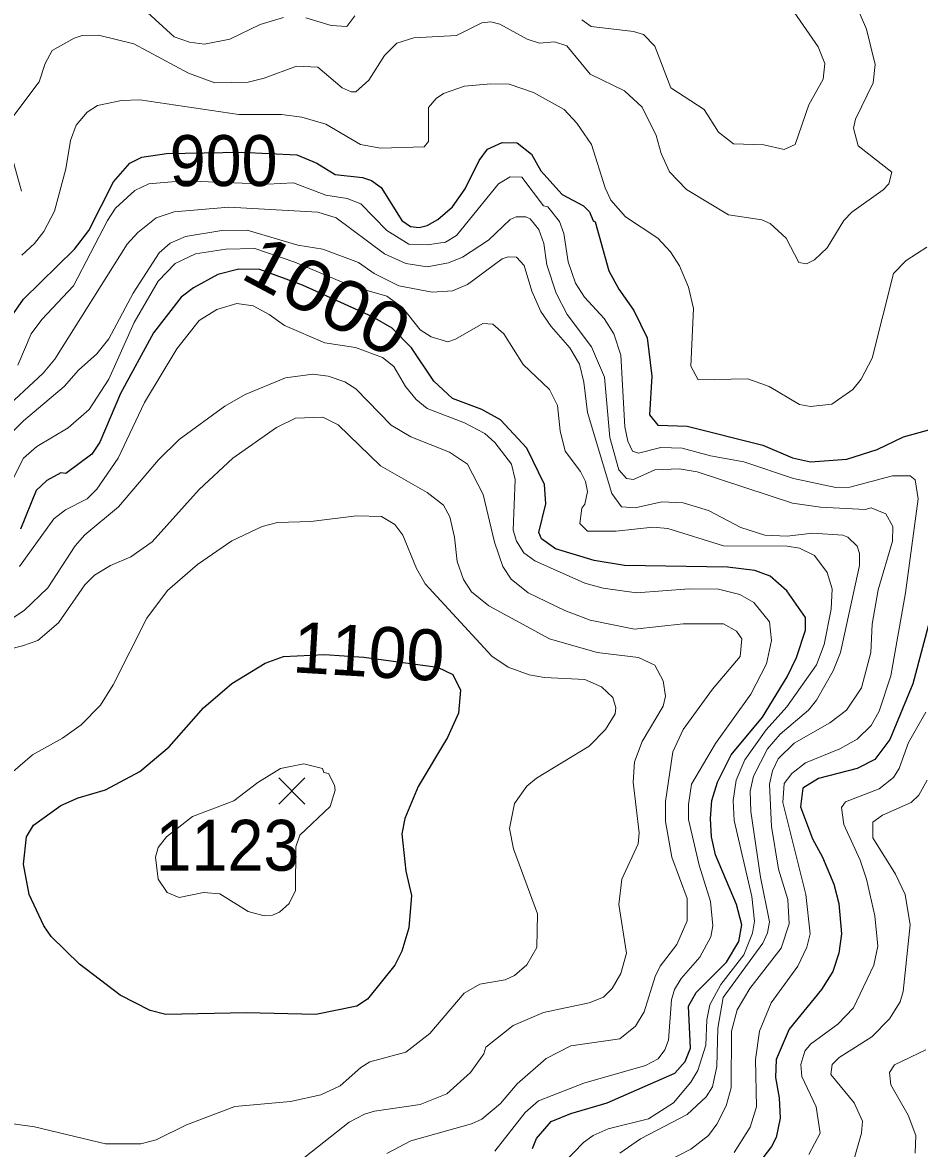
# Model space of a CAD drawing. Extents: x 265 to 291.4, y 7731.5 to 7759.6.
# Drawn here: x 282.452 to 283.863, y 7748.958 to 7750.728 of the extents above; entities that cross this region are included whole.
import ezdxf
from ezdxf.enums import TextEntityAlignment as Align

# ---------------------------------------------------------------- set-up
doc = ezdxf.new("R2010")
doc.units = 0
doc.header["$LTSCALE"] = 0.032
for name, color, linetype, lineweight in [('1', 7, 'Continuous', 25), ('2', 7, 'Continuous', 13), ('21', 7, 'Continuous', 25), ('61', 7, 'Continuous', 13)]:
    doc.layers.add(name, color=color, linetype=linetype, lineweight=lineweight)

msp = doc.modelspace()

# ---------------------------------------------------------------- linework, layer by layer
at = {"layer": '1'}
for points in [[(282.3987, 7750.2149), (282.4536, 7750.2929), (282.534, 7750.3716), (282.5562, 7750.401), (282.5952, 7750.4774), (282.6207, 7750.5068), (282.6398, 7750.5164), (282.6787, 7750.522), (282.7963, 7750.524), (282.8837, 7750.5201), (282.915, 7750.5068), (282.9436, 7750.4893), (282.9866, 7750.4845), (283.0009, 7750.4798), (283.016, 7750.4686), (283.0486, 7750.4169), (283.0622, 7750.4074), (283.0757, 7750.4058), (283.0884, 7750.409), (283.1051, 7750.4185), (283.1282, 7750.4384), (283.1481, 7750.4663), (283.1703, 7750.5108), (283.1831, 7750.5291), (283.2062, 7750.5394), (283.23, 7750.5386), (283.2523, 7750.5211), (283.2674, 7750.4949), (283.3008, 7750.4575), (283.3342, 7750.44), (283.3438, 7750.4304), (283.3493, 7750.4161), (283.3525, 7750.4146), (283.374, 7750.3374), (283.3899, 7750.3088), (283.4137, 7750.2754), (283.4344, 7750.2324), (283.4416, 7750.1719), (283.4384, 7750.1115), (283.4511, 7750.0948), (283.4973, 7750.0932), (283.6166, 7750.0637), (283.6628, 7750.0438), (283.6914, 7750.0375), (283.7487, 7750.0415), (283.7964, 7750.0566), (283.8377, 7750.0765), (283.8775, 7750.0876)], [(283.2539, 7748.958), (283.2602, 7748.9739), (283.2833, 7749.0002), (283.3143, 7749.0129), (283.3716, 7749.0296), (283.4782, 7749.0765), (283.4941, 7749.0949), (283.5028, 7749.1155), (283.4997, 7749.1815), (283.5116, 7749.203), (283.5593, 7749.2507), (283.5784, 7749.2834), (283.5832, 7749.3096), (283.5752, 7749.3415), (283.5418, 7749.4194), (283.5355, 7749.448), (283.5339, 7749.4767), (283.5363, 7749.5053), (283.545, 7749.534), (283.5665, 7749.5769), (283.6158, 7749.6358), (283.6548, 7749.6994), (283.6691, 7749.7296), (283.6834, 7749.7726), (283.6834, 7749.7925), (283.654, 7749.8347), (283.6277, 7749.8577), (283.6039, 7749.8664), (283.5609, 7749.872), (283.3987, 7749.8744), (283.3509, 7749.8824), (283.2905, 7749.9006), (283.2682, 7749.9166), (283.2642, 7749.9261), (283.2753, 7749.9715), (283.2729, 7750.0017), (283.2451, 7750.059), (283.2037, 7750.1035), (283.1743, 7750.1194), (283.1282, 7750.1369), (283.0987, 7750.164), (283.0637, 7750.2165), (283.0335, 7750.2475), (283.0027, 7750.2654), (282.8924, 7750.3153), (282.8254, 7750.3398), (282.7925, 7750.3405), (282.7591, 7750.3318), (282.7209, 7750.3111), (282.7018, 7750.296), (282.658, 7750.2404), (282.6063, 7750.1449), (282.5737, 7750.0685), (282.561, 7750.0494), (282.5204, 7750.0192), (282.5125, 7750.02), (282.4902, 7750.008), (282.4735, 7749.9921), (282.4488, 7749.9317)], [(283.8807, 7749.7949), (283.8521, 7749.6883), (283.8163, 7749.6008), (283.7924, 7749.5697), (283.7646, 7749.5554), (283.7041, 7749.5395), (283.6794, 7749.5244), (283.6755, 7749.495), (283.6946, 7749.4449), (283.7105, 7749.4162), (283.728, 7749.3733), (283.7359, 7749.343), (283.7399, 7749.2953), (283.7359, 7749.2651), (283.7264, 7749.2364), (283.7089, 7749.2078), (283.658, 7749.1458), (283.6373, 7749.098), (283.6365, 7749.0694), (283.6421, 7749.0376), (283.6436, 7749.0058), (283.6373, 7748.9755), (283.6301, 7748.9612), (283.5959, 7748.9166)]]:
    msp.add_lwpolyline(points, dxfattribs=at)
msp.add_lwpolyline([(282.6774, 7749.1687), (282.6526, 7749.1749), (282.6055, 7749.199), (282.5419, 7749.2476), (282.4973, 7749.2913), (282.4854, 7749.308), (282.4624, 7749.3574), (282.4536, 7749.4051), (282.4584, 7749.448), (282.4695, 7749.4663), (282.5125, 7749.4973), (282.5395, 7749.5093), (282.5825, 7749.522), (282.6366, 7749.5506), (282.6827, 7749.5896), (282.7368, 7749.6509), (282.7814, 7749.689), (282.8339, 7749.7209), (282.8625, 7749.7312), (282.9269, 7749.7344), (282.9887, 7749.7304), (283.1049, 7749.7145), (283.1288, 7749.7032), (283.1409, 7749.6787), (283.1377, 7749.6421), (283.1202, 7749.604), (283.0741, 7749.5268), (283.0534, 7749.4767), (283.0486, 7749.4528), (283.055, 7749.394), (283.0637, 7749.3558), (283.0598, 7749.3049), (283.0486, 7749.2683), (283.0375, 7749.246), (282.9945, 7749.1927), (282.9778, 7749.1815), (282.9134, 7749.1688), (282.8036, 7749.1712)], close=True, dxfattribs=at)
at = {"layer": '2'}
for points in [[(282.4989, 7750.6842), (282.5332, 7750.7033), (282.5459, 7750.7073), (282.5714, 7750.7081), (282.627, 7750.6946), (282.713, 7750.6484), (282.7543, 7750.6333), (282.8068, 7750.6341), (282.8323, 7750.6405), (282.8832, 7750.6596), (282.9166, 7750.658), (282.9548, 7750.6253), (282.9691, 7750.619), (282.9762, 7750.619), (282.9969, 7750.6373), (283.0216, 7750.6763), (283.0407, 7750.6953), (283.0677, 7750.7041), (283.1346, 7750.7073), (283.1743, 7750.7272), (283.1887, 7750.7288), (283.203, 7750.7256), (283.2459, 7750.7017), (283.265, 7750.6953), (283.2889, 7750.6977), (283.308, 7750.6914), (283.3446, 7750.6468), (283.3987, 7750.6206), (283.4265, 7750.5951), (283.4488, 7750.5506), (283.4567, 7750.522), (283.4694, 7750.4933), (283.4965, 7750.4655), (283.5625, 7750.4257), (283.615, 7750.4177), (283.6278, 7750.4122), (283.6532, 7750.3891), (283.6731, 7750.3509), (283.685, 7750.3485), (283.6978, 7750.3549), (283.7176, 7750.374), (283.7439, 7750.4169), (283.7566, 7750.4297), (283.8059, 7750.4647), (283.8147, 7750.4742), (283.8195, 7750.4925), (283.7662, 7750.5339), (283.759, 7750.5617), (283.7622, 7750.576), (283.79, 7750.6333), (283.7932, 7750.662), (283.7797, 7750.7176), (283.7574, 7750.7686)], [(283.6516, 7750.7654), (283.7033, 7750.6898), (283.7137, 7750.6635), (283.7113, 7750.6389), (283.689, 7750.5983), (283.6675, 7750.5363), (283.65, 7750.5283), (283.6182, 7750.5355), (283.5705, 7750.5371), (283.5466, 7750.5554), (283.5243, 7750.5912), (283.4718, 7750.6254), (283.4464, 7750.6906), (283.4289, 7750.7089), (283.413, 7750.7137), (283.3462, 7750.7216), (283.3318, 7750.732)], [(282.8625, 7750.7359), (282.8259, 7750.7248), (282.7782, 7750.7017), (282.7384, 7750.6938), (282.7145, 7750.6969), (282.6907, 7750.7057), (282.631, 7750.7598)], [(282.9747, 7750.7383), (282.9619, 7750.7216), (282.9373, 7750.7232), (282.8975, 7750.7351)], [(282.4504, 7750.4631), (282.4305, 7750.5347), (282.429, 7750.549), (282.4353, 7750.5776), (282.4783, 7750.6349), (282.4878, 7750.6635), (282.4989, 7750.6842)], [(283.8744, 7750.3748), (283.8417, 7750.3541), (283.8219, 7750.3334), (283.7884, 7750.2006), (283.7709, 7750.1672), (283.7582, 7750.1512), (283.7248, 7750.1282), (283.6914, 7750.1242), (283.6739, 7750.1274), (283.6262, 7750.156), (283.5928, 7750.1679), (283.5148, 7750.1664), (283.5029, 7750.1878), (283.5076, 7750.2785), (283.4997, 7750.3119), (283.4854, 7750.3454), (283.471, 7750.3676), (283.4511, 7750.3891), (283.4003, 7750.4225), (283.3772, 7750.4488), (283.3684, 7750.4679), (283.3469, 7750.5363), (283.3239, 7750.5697), (283.304, 7750.5912), (283.2555, 7750.6182), (283.2173, 7750.6309), (283.1887, 7750.6317), (283.1473, 7750.6277), (283.1139, 7750.6166), (283.1027, 7750.6086), (283.0908, 7750.5943), (283.0908, 7750.541), (283.0836, 7750.5323), (283.0152, 7750.5307), (282.9834, 7750.5363), (282.9293, 7750.5681), (282.8911, 7750.5792), (282.8593, 7750.5832), (282.7925, 7750.5832), (282.6366, 7750.6063), (282.6079, 7750.6055), (282.5697, 7750.5975), (282.5539, 7750.5872), (282.5363, 7750.5665), (282.5276, 7750.5426), (282.5204, 7750.4981), (282.5021, 7750.4313), (282.4854, 7750.3994), (282.4711, 7750.3804), (282.4512, 7750.3621)], [(282.4449, 7750.1894), (282.4655, 7750.2388), (282.4822, 7750.261), (282.5324, 7750.3143), (282.5857, 7750.4169), (282.5984, 7750.436), (282.6286, 7750.4639), (282.6509, 7750.4742), (282.7046, 7750.4793), (282.8371, 7750.474), (282.8784, 7750.4758), (282.9293, 7750.4567), (282.9627, 7750.4511), (282.9842, 7750.4432), (283.0248, 7750.401), (283.0598, 7750.3795), (283.0884, 7750.3787), (283.1171, 7750.3827), (283.1346, 7750.3931), (283.2006, 7750.4742), (283.2189, 7750.4853), (283.2372, 7750.4846), (283.2714, 7750.44), (283.2785, 7750.4384), (283.2968, 7750.4154), (283.3032, 7750.3963), (283.3103, 7750.3517), (283.3215, 7750.3183), (283.3358, 7750.296), (283.3668, 7750.2626), (283.3819, 7750.2388), (283.3931, 7750.2053), (283.3994, 7750.0924), (283.4042, 7750.0701), (283.4114, 7750.0542), (283.4209, 7750.051), (283.4559, 7750.0598), (283.4893, 7750.059), (283.5339, 7750.047), (283.5864, 7750.0375), (283.6644, 7750.0112), (283.7312, 7749.9969), (283.7534, 7749.9977), (283.8203, 7750.0152), (283.8481, 7750.0152), (283.8561, 7750.0089), (283.8608, 7749.9794), (283.8409, 7749.8315), (283.8179, 7749.701), (283.7996, 7749.6453), (283.7868, 7749.6231), (283.7646, 7749.6016), (283.7375, 7749.5864), (283.6834, 7749.5642), (283.662, 7749.5475), (283.65, 7749.5316), (283.6476, 7749.5021), (283.6842, 7749.3574), (283.6906, 7749.2953), (283.6858, 7749.2746), (283.6715, 7749.2444), (283.6293, 7749.1871), (283.611, 7749.1426), (283.6047, 7749.098), (283.6063, 7749.0233), (283.5967, 7748.9914), (283.5713, 7748.9517)], [(283.5585, 7749.0249), (283.5665, 7749.0535), (283.5673, 7749.1426), (283.576, 7749.176), (283.5959, 7749.2094), (283.6452, 7749.273), (283.658, 7749.3112), (283.6556, 7749.3494), (283.6413, 7749.3971), (283.6301, 7749.464), (283.627, 7749.5308), (283.6317, 7749.5515), (283.6405, 7749.5706), (283.6659, 7749.5952), (283.7216, 7749.627), (283.7479, 7749.6469), (283.7717, 7749.6819), (283.7861, 7749.7376), (283.7884, 7749.7822), (283.798, 7749.8362), (283.8203, 7749.9126), (283.821, 7749.9357), (283.8099, 7749.9556), (283.7869, 7749.9651), (283.7773, 7749.9627), (283.7073, 7749.9659), (283.6628, 7749.9723), (283.5132, 7750.0216), (283.4846, 7750.0264), (283.4464, 7750.0248), (283.413, 7750.0096), (283.4018, 7750.0112), (283.3899, 7750.0248), (283.3756, 7750.0757), (283.3676, 7750.1703), (283.3469, 7750.2181), (283.3088, 7750.269), (283.2913, 7750.3024), (283.2769, 7750.3469), (283.2722, 7750.3804), (283.2642, 7750.4026), (283.2507, 7750.4193), (283.2435, 7750.4225), (283.2284, 7750.4225), (283.2189, 7750.4185), (283.1847, 7750.3859), (283.1441, 7750.3589), (283.1218, 7750.3501), (283.0884, 7750.3437), (283.055, 7750.3493), (283.0216, 7750.3644), (282.9452, 7750.4209), (282.9166, 7750.4297), (282.7766, 7750.4376), (282.6907, 7750.4305), (282.662, 7750.4209), (282.6334, 7750.3978), (282.6167, 7750.3795), (282.5029, 7750.199), (282.4846, 7750.1767), (282.417, 7750.1139)], [(282.378, 7750.0272), (282.4536, 7750.1019), (282.5173, 7750.156), (282.5403, 7750.1815), (282.569, 7750.2069), (282.588, 7750.2308), (282.6262, 7750.3024), (282.6668, 7750.366), (282.6843, 7750.3811), (282.7082, 7750.3915), (282.7655, 7750.401), (282.8052, 7750.4018), (282.8848, 7750.378), (282.9246, 7750.3716), (282.9802, 7750.3509), (283.0049, 7750.3334), (283.0439, 7750.3143), (283.0964, 7750.304), (283.1282, 7750.3064), (283.1521, 7750.3159), (283.2062, 7750.3565), (283.2157, 7750.3597), (283.2292, 7750.3589), (283.2411, 7750.3461), (283.2531, 7750.3056), (283.2674, 7750.2738), (283.2833, 7750.2499), (283.3127, 7750.2165), (283.3278, 7750.191), (283.335, 7750.1624), (283.3406, 7750.1147), (283.3788, 7749.9874), (283.3939, 7749.9667), (283.4154, 7749.9651), (283.4575, 7749.9746), (283.4909, 7749.9731), (283.5307, 7749.9611), (283.5816, 7749.9341), (283.6198, 7749.9221), (283.6548, 7749.9205), (283.6946, 7749.9253), (283.7423, 7749.9221), (283.7503, 7749.919), (283.7646, 7749.9046), (283.7685, 7749.8935), (283.7685, 7749.8744), (283.7383, 7749.7376), (283.7272, 7749.709), (283.7009, 7749.6628)], [(283.5744, 7749.5371), (283.588, 7749.569), (283.6214, 7749.6159), (283.654, 7749.6525), (283.7009, 7749.7185), (283.7129, 7749.7503), (283.724, 7749.806), (283.7256, 7749.8378), (283.7176, 7749.8633), (283.6978, 7749.8903), (283.6739, 7749.9015), (283.6548, 7749.9046), (283.5546, 7749.9054), (283.4671, 7749.9325), (283.4432, 7749.9349), (283.3859, 7749.9285), (283.3406, 7749.9285), (283.3286, 7749.9404), (283.3318, 7749.9643), (283.3366, 7749.9707), (283.3406, 7749.9906), (283.3374, 7750.0065), (283.3294, 7750.0224), (283.3056, 7750.0542), (283.2976, 7750.086), (283.2936, 7750.1258), (283.2809, 7750.1513), (283.2396, 7750.1902), (283.2093, 7750.2388), (283.1918, 7750.2539), (283.1759, 7750.2547), (283.133, 7750.23), (283.121, 7750.226), (283.0948, 7750.234), (283.0773, 7750.2451), (283.0494, 7750.2801), (283.0248, 7750.2976), (282.9683, 7750.3143), (282.8805, 7750.3514), (282.8176, 7750.3726), (282.7718, 7750.3716), (282.7241, 7750.3644), (282.6923, 7750.3493), (282.6652, 7750.3215), (282.6278, 7750.2563), (282.588, 7750.1672), (282.557, 7750.1194), (282.5236, 7750.0908), (282.4743, 7750.0614), (282.4536, 7750.0431), (282.421, 7749.9794)], [(282.4473, 7749.8728), (282.5013, 7749.9476), (282.5196, 7749.9619), (282.5539, 7749.9794), (282.569, 7749.9945), (282.6024, 7750.0431), (282.6437, 7750.1306), (282.6946, 7750.2149), (282.7296, 7750.2594), (282.7575, 7750.2769), (282.7893, 7750.2865), (282.8148, 7750.2825), (282.8402, 7750.269), (282.8641, 7750.2515), (282.9277, 7750.2244), (282.9755, 7750.2173), (283.0184, 7750.2014), (283.0359, 7750.187), (283.0542, 7750.156), (283.0709, 7750.1353), (283.0884, 7750.121), (283.1473, 7750.0987), (283.1791, 7750.082), (283.195, 7750.0677), (283.2213, 7750.0335), (283.2268, 7750.0097), (283.2236, 7749.9301), (283.2292, 7749.9126), (283.2403, 7749.8943), (283.2578, 7749.8816), (283.3366, 7749.8466), (283.3652, 7749.8386), (283.4178, 7749.8315), (283.5005, 7749.8378), (283.5466, 7749.837), (283.58, 7749.8291), (283.6023, 7749.8163), (283.627, 7749.7861), (283.6301, 7749.7567), (283.6222, 7749.7201), (283.5975, 7749.6724), (283.5418, 7749.5944), (283.5044, 7749.5308), (283.4997, 7749.499), (283.4997, 7749.4751), (283.5164, 7749.4035), (283.5339, 7749.3462), (283.5379, 7749.308), (283.5347, 7749.2905), (283.5172, 7749.2587), (283.4877, 7749.2253), (283.4774, 7749.2078), (283.4726, 7749.1919), (283.4679, 7749.1283), (283.4623, 7749.1131), (283.452, 7749.0988), (283.4321, 7749.0885), (283.335, 7749.0606), (283.2634, 7749.0328), (283.2427, 7749.0145), (283.195, 7748.954)], [(283.2077, 7749.8728), (283.1942, 7749.911), (283.1767, 7749.9858), (283.152, 7750.0335), (283.1234, 7750.0526), (283.063, 7750.0765), (283.0319, 7750.0948), (282.9763, 7750.152), (282.9588, 7750.1632), (282.9325, 7750.1719), (282.9086, 7750.1751), (282.8657, 7750.1695), (282.802, 7750.1433), (282.7702, 7750.125), (282.6986, 7750.0725), (282.666, 7750.0407), (282.6032, 7749.9667), (282.5499, 7749.9229), (282.5348, 7749.9054), (282.4918, 7749.8394), (282.4544, 7749.8036), (282.4314, 7749.7885)], [(282.3613, 7749.7249), (282.452, 7749.7479), (282.4759, 7749.7567), (282.5085, 7749.7845), (282.5499, 7749.8442), (282.565, 7749.8593), (282.5904, 7749.8744), (282.6223, 7749.8879), (282.6557, 7749.9118), (282.7296, 7749.9937), (282.7829, 7750.0431), (282.8514, 7750.0916), (282.8816, 7750.1059), (282.9246, 7750.1075), (282.9484, 7750.0956), (283.0152, 7750.0311), (283.0884, 7749.989), (283.1139, 7749.9691), (283.1242, 7749.9508), (283.1314, 7749.919), (283.1354, 7749.8808), (283.1457, 7749.8522), (283.1584, 7749.8331), (283.1855, 7749.8108), (283.2809, 7749.7591), (283.3557, 7749.7376), (283.4209, 7749.7296), (283.4464, 7749.7177), (283.4599, 7749.6931), (283.4631, 7749.6692), (283.4599, 7749.6533), (283.4265, 7749.5976), (283.4146, 7749.5658), (283.4122, 7749.534), (283.4217, 7749.4544), (283.4201, 7749.4369), (283.3947, 7749.3812), (283.3899, 7749.3415), (283.4018, 7749.2651), (283.3931, 7749.2333), (283.3796, 7749.2094), (283.366, 7749.1959), (283.343, 7749.1871), (283.2714, 7749.172), (283.2237, 7749.1513), (283.1807, 7749.1171), (283.1775, 7749.1068), (283.1568, 7749.0774), (283.1194, 7749.0439), (283.0773, 7749.0272), (283.0057, 7749.0169), (282.9898, 7749.0121), (282.9659, 7748.9994), (282.8959, 7748.9445)], [(282.3995, 7749.0018), (282.4711, 7748.9922), (282.5825, 7748.9652), (282.6382, 7748.9652), (282.662, 7748.9715), (282.7098, 7748.9954), (282.7861, 7749.024), (282.8736, 7749.032), (282.9214, 7749.0423), (282.9516, 7749.0567), (282.9842, 7749.0853), (282.9985, 7749.094), (283.055, 7749.1092), (283.0924, 7749.1386), (283.1465, 7749.2022), (283.1712, 7749.2165), (283.2109, 7749.2229), (283.226, 7749.2301), (283.2451, 7749.2468), (283.261, 7749.2738), (283.2618, 7749.3271), (283.2244, 7749.429), (283.2181, 7749.4608), (283.226, 7749.5005), (283.2451, 7749.5276), (283.2602, 7749.5403), (283.343, 7749.5904), (283.3692, 7749.6167), (283.3843, 7749.6413), (283.3851, 7749.6509), (283.3803, 7749.6668), (283.3629, 7749.6835), (283.3366, 7749.6954), (283.273, 7749.6986), (283.2491, 7749.7026), (283.2157, 7749.7145), (283.1902, 7749.732), (283.0852, 7749.8458), (283.0717, 7749.8697), (283.0502, 7749.9222), (283.0375, 7749.9389), (283.0168, 7749.9516), (282.9771, 7749.9524), (282.9055, 7749.9436), (282.853, 7749.942), (282.8291, 7749.9357), (282.7814, 7749.9134), (282.7273, 7749.876), (282.6803, 7749.8354), (282.6477, 7749.7917), (282.5944, 7749.6867), (282.5745, 7749.6549), (282.5443, 7749.6238), (282.5149, 7749.6032), (282.4679, 7749.5769), (282.429, 7749.5435)], [(283.4909, 7749.7829), (283.4146, 7749.7742), (283.3446, 7749.7885), (283.3048, 7749.8036), (283.2475, 7749.8315), (283.2205, 7749.8529), (283.2077, 7749.8728)], [(283.0248, 7748.9501), (283.063, 7748.9699), (283.1584, 7748.997), (283.1743, 7749.0041), (283.2038, 7749.0288), (283.23, 7749.0599), (283.2754, 7749.0996), (283.3143, 7749.1195), (283.3915, 7749.1306), (283.4162, 7749.1505), (283.4297, 7749.1728), (283.4472, 7749.2285), (283.4551, 7749.2444), (283.4814, 7749.2786), (283.4973, 7749.316), (283.4973, 7749.351), (283.4734, 7749.4162), (283.4631, 7749.4719), (283.4631, 7749.5037), (283.475, 7749.5817), (283.4909, 7749.6167), (283.5371, 7749.6803), (283.5808, 7749.7312), (283.5832, 7749.7591), (283.5752, 7749.771), (283.5546, 7749.7829), (283.4909, 7749.7829)], [(283.7009, 7749.6628), (283.6882, 7749.6469), (283.6437, 7749.6095), (283.6238, 7749.5865), (283.6015, 7749.5435), (283.5967, 7749.5196), (283.5975, 7749.4878)], [(283.689, 7748.9485), (283.7065, 7748.9819), (283.7001, 7749.0233), (283.6779, 7749.071), (283.6763, 7749.0901), (283.6826, 7749.1108), (283.6914, 7749.1219), (283.7344, 7749.1537), (283.759, 7749.1792), (283.7908, 7749.246), (283.7972, 7749.2762), (283.7924, 7749.324), (283.7797, 7749.3812), (283.7693, 7749.4115), (283.7439, 7749.4671), (283.7399, 7749.4942), (283.7463, 7749.5029), (283.7996, 7749.5236), (283.8218, 7749.5411), (283.8306, 7749.5554), (283.8457, 7749.596), (283.8728, 7749.6437)], [(283.5867, 7749.2622), (283.5999, 7749.2967), (283.6032, 7749.3152), (283.5991, 7749.3542), (283.5713, 7749.4735), (283.5697, 7749.5053), (283.5744, 7749.5371)], [(283.8751, 7749.5371), (283.8616, 7749.5133), (283.8497, 7749.5021), (283.8044, 7749.4822), (283.7892, 7749.4711), (283.7892, 7749.4465), (283.825, 7749.3892), (283.8401, 7749.3574), (283.8481, 7749.3096), (283.837, 7749.2046), (283.8322, 7749.1887), (283.8155, 7749.1617), (283.7876, 7749.1338), (283.7367, 7749.1012)], [(283.5975, 7749.4878), (283.6126, 7749.3844), (283.627, 7749.3144), (283.6238, 7749.2969), (283.6166, 7749.281), (283.5538, 7749.1956), (283.5458, 7749.1474), (283.5442, 7749.0869), (283.5371, 7749.0551), (283.5275, 7749.0392), (283.4973, 7749.0113), (283.4241, 7748.9731), (283.3915, 7748.9509)], [(283.2698, 7748.9007), (283.3342, 7748.9676), (283.3493, 7748.9787), (283.3732, 7748.989), (283.4368, 7749.0049), (283.4758, 7749.0296), (283.5029, 7749.0622), (283.514, 7749.0805), (283.5267, 7749.1203), (283.5283, 7749.1601), (283.5331, 7749.1839), (283.5506, 7749.2158), (283.5867, 7749.2622)], [(283.7367, 7749.1012), (283.7256, 7749.0901), (283.7232, 7749.0742), (283.7598, 7749.0296), (283.7733, 7749.001), (283.7717, 7748.9819), (283.7582, 7748.9342)], [(283.8561, 7748.9509), (283.8569, 7748.9787), (283.8449, 7749.0105), (283.8179, 7749.0583), (283.8155, 7749.0774), (283.8234, 7749.0893), (283.8728, 7749.1131)], [(283.3462, 7748.8387), (283.4042, 7748.9), (283.4448, 7748.927), (283.5029, 7748.9572), (283.5307, 7748.9787), (283.5442, 7748.9962), (283.5585, 7749.0249)]]:
    msp.add_lwpolyline(points, dxfattribs=at)
msp.add_lwpolyline([(282.8818, 7749.432), (282.8884, 7749.4506), (282.9357, 7749.4957), (282.9436, 7749.5212), (282.9428, 7749.5292), (282.9333, 7749.5475), (282.9261, 7749.5491), (282.9238, 7749.5554), (282.8943, 7749.5626), (282.8577, 7749.5554), (282.8219, 7749.5332), (282.7845, 7749.5045), (282.7193, 7749.4798), (282.6787, 7749.4479), (282.6654, 7749.4313), (282.6612, 7749.4162), (282.6652, 7749.3812), (282.6795, 7749.3605), (282.6986, 7749.3526), (282.7368, 7749.3605), (282.7623, 7749.3581), (282.8068, 7749.3303), (282.8323, 7749.3239), (282.845, 7749.3247), (282.8561, 7749.3295), (282.8712, 7749.343), (282.8816, 7749.3637)], close=True, dxfattribs=at)
at = {"layer": '21'}
for p, q in [((282.8551, 7749.5405), (282.8963, 7749.4993)), ((282.8963, 7749.5405), (282.8551, 7749.4993))]:
    msp.add_line(p, q, dxfattribs=at)

# ---------------------------------------------------------------- texts
at = {"layer": '61', "width": 0.95}
for s, p in [('900', (282.7683, 7750.4709)), ('1123', (282.7744, 7749.3947))]:
    msp.add_text(s, height=0.08, dxfattribs=at).set_placement(p, align=Align.CENTER)
at = {"layer": '61', "width": 1.15}
msp.add_text('1000', height=0.08, rotation=331.986, dxfattribs=at).set_placement((282.9128, 7750.2631), align=Align.CENTER)
at = {"layer": '61'}
msp.add_text('1100', height=0.08, rotation=356.569, dxfattribs=at).set_placement((282.9943, 7749.6995), align=Align.CENTER)

doc.saveas('drawing.dxf')
